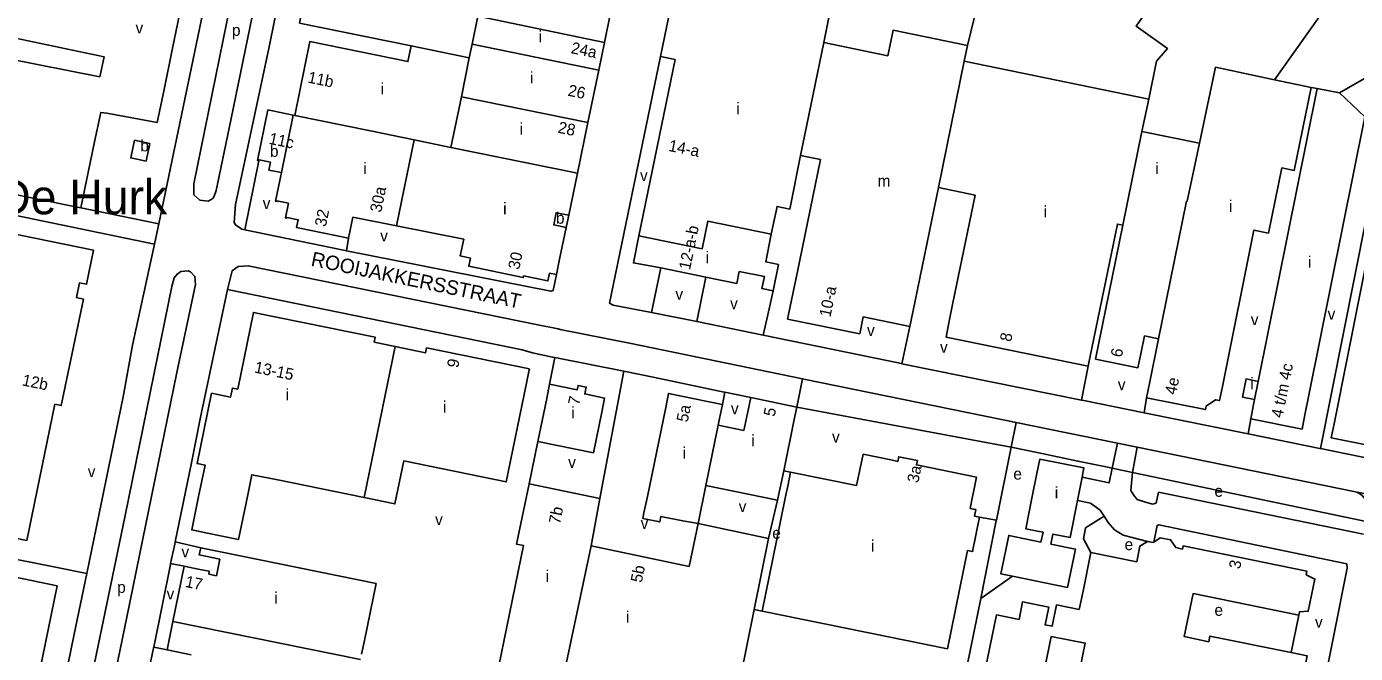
# Model space of a CAD drawing. Extents: x 157699 to 159683, y 381451 to 383293.
# Drawn here: x 158508.3 to 158968.6, y 382195.6 to 382412.9 of the extents above; entities that cross this region are included whole.
import ezdxf

# ---------------------------------------------------------------- set-up
doc = ezdxf.new("R2010")
doc.units = 0
for name, color, linetype in [('BLT_Basislijn', 7, 'Continuous'), ('BLT_Bebouwing', 7, 'Continuous'), ('BLT_Centroide', 7, 'Continuous'), ('BLT_Huisnummer', 7, 'Continuous'), ('BLT_Huisnummer_reeks', 7, 'Continuous'), ('BLT_Onderverdeling_panden', 7, 'Continuous'), ('BLT_Sport_parknaam', 7, 'Continuous'), ('BLT_Straatnaam', 7, 'Continuous')]:
    doc.layers.add(name, color=color, linetype=linetype)

msp = doc.modelspace()

# ---------------------------------------------------------------- linework, layer by layer
at = {"layer": 'BLT_Basislijn'}
for p, q in [((158572.61, 382433.33), (158554.1, 382344.5)), ((158562.84, 382424.73), (158558.87, 382405.41)), ((158834.2, 382406.33), (158836.48, 382415.8)), ((158986.18, 382403.27), (158963.05, 382389.93)), ((158953.3, 382391.8), (158955.38, 382391.47)), ((158583.87, 382342.43), (158588.74, 382366.35)), ((158501.45, 382355.29), (158511.7, 382353.19)), ((158486.34, 382351.12), (158552.63, 382337.43)), ((158511.7, 382353.19), (158522.43, 382350.98)), ((158522.43, 382350.98), (158527.1, 382350)), ((158527.1, 382350), (158554.1, 382344.5)), ((158552.63, 382337.43), (158554.1, 382344.5)), ((158619.84, 382339.52), (158619.06, 382335.14)), ((158727.99, 382329.23), (158724.76, 382313.76)), ((158743.57, 382326.04), (158740.43, 382310.59)), ((158765, 382312.9), (158766.85, 382321.28)), ((158724.76, 382313.76), (158740.43, 382310.59)), ((158763.45, 382305.87), (158765, 382312.9)), ((158740.43, 382310.59), (158763.45, 382305.87)), ((158814.26, 382308.95), (158811.51, 382296.02)), ((158717.11, 382303.09), (158693.17, 382307.91)), ((158717.11, 382303.09), (158777.08, 382290.77)), ((158689.44, 382288.89), (158691.25, 382298.12)), ((158715.13, 382293.41), (158691.25, 382298.12)), ((158811.51, 382296.02), (158873.68, 382283.41)), ((158876.04, 382295.15), (158873.68, 382283.41)), ((158715.13, 382293.41), (158706.81, 382249.34)), ((158715.13, 382293.41), (158725.36, 382291.29)), ((158775.06, 382281), (158777.08, 382290.77)), ((158749.35, 382281.86), (158750.19, 382286.1)), ((158750.19, 382286.1), (158759.11, 382284.26)), ((158775.06, 382281), (158849.34, 382267.03)), ((158895.4, 382278.98), (158896.26, 382284.2)), ((158931.38, 382271.66), (158895.4, 382278.98)), ((158931.38, 382271.66), (158932.33, 382276.93)), ((158849.34, 382267.03), (158851.05, 382275.67)), ((158886.21, 382268.5), (158851.05, 382275.67)), ((158682.37, 382254.34), (158685.39, 382269.09)), ((158844.21, 382241.74), (158849.34, 382267.03)), ((158884.34, 382259.75), (158886.21, 382268.5)), ((158886.21, 382268.5), (158893.02, 382267.13)), ((158891.33, 382258.3), (158893.02, 382267.13)), ((158968.06, 382251.75), (158893.02, 382267.13)), ((158956.46, 382266.56), (158986.47, 382260.39)), ((158772.93, 382258.45), (158770.53, 382258.89)), ((158881.04, 382260.49), (158884.34, 382259.75)), ((158884.34, 382259.75), (158891.33, 382258.3)), ((158891.33, 382258.3), (158890.77, 382252.04)), ((158891.33, 382258.3), (158972.31, 382241.32)), ((158765.25, 382235.43), (158768.45, 382248.7)), ((158890.77, 382252.04), (158891.74, 382250.55)), ((158891.74, 382250.55), (158893.01, 382248.98)), ((158893.01, 382248.98), (158895.47, 382248.09)), ((158899.57, 382247.64), (158900.34, 382251.44)), ((158971.38, 382236.96), (158900.34, 382251.44)), ((158968.06, 382251.75), (158980.78, 382249.13)), ((158895.47, 382248.09), (158898.3, 382247.27)), ((158898.3, 382247.27), (158899.57, 382247.64)), ((158838.39, 382242.79), (158844.21, 382241.74)), ((158479.27, 382233.29), (158518.84, 382225.38)), ((158568.64, 382232.22), (158559.74, 382234.23)), ((158518.84, 382225.38), (158529.12, 382223.33)), ((158562.88, 382225.83), (158558.18, 382226.72)), ((158529.12, 382223.33), (158524.79, 382202.3)), ((158824.7, 382145.3), (158838.81, 382214.57)), ((158763.08, 382210.26), (158760.28, 382210.83)), ((158946.27, 382195.85), (158949.01, 382208.79)), ((158556.95, 382196.78), (158552.33, 382197.7))]:
    msp.add_line(p, q, dxfattribs=at)
for points in [[(158533.71, 382395.49), (158535.16, 382402.41), (158495.57, 382410.69), (158488.96, 382420.8), (158500.45, 382475.74)], [(158589.92, 382433.33), (158595.48, 382460.27), (158595.51, 382461.5), (158594.69, 382463.74), (158593.67, 382464.66), (158590.55, 382465.32), (158589.18, 382464.95), (158587.53, 382462.82), (158581.51, 382433.33), (158566.21, 382358.35), (158566.28, 382354.58), (158568.34, 382352.66), (158571.2, 382352.4), (158572.77, 382353.27), (158573.3, 382354.15), (158574, 382356.06), (158578.99, 382380.49), (158589.92, 382433.33)], [(158583.87, 382342.43), (158582.82, 382342.64), (158580.69, 382344.1), (158580.25, 382344.99), (158580.69, 382351.18), (158592.27, 382405.81), (158597.9, 382433.33), (158604.02, 382463.33)], [(158558.87, 382405.41), (158555.91, 382391.09)], [(158533.71, 382395.49), (158501.04, 382401.96), (158495.93, 382377.87)], [(158727.91, 382402.53), (158710.19, 382317.05), (158711.49, 382316.32), (158724.76, 382313.76)], [(158555.91, 382391.09), (158553.54, 382379.67), (158536.07, 382382.87)], [(158536.07, 382382.87), (158533.96, 382383.11), (158531.86, 382372.98)], [(158531.86, 382372.98), (158527.1, 382350)], [(158978.31, 382375.44), (158972.33, 382346.27), (158956.46, 382266.56)], [(158619.06, 382335.14), (158618.11, 382335.33), (158583.87, 382342.43)], [(158544.99, 382302.39), (158552.63, 382337.43)], [(158619.06, 382335.14), (158689.84, 382321.11), (158690.7, 382321.39), (158691.8, 382326.9)], [(158542.98, 382208.18), (158560.31, 382292.99), (158566.84, 382323.44), (158566.59, 382326.28), (158565.09, 382327.85), (158564.24, 382328.17), (158561.69, 382328.03), (158560.4, 382327.07), (158559.37, 382325.83), (158558.61, 382322.72), (158542.49, 382243.35), (158519.79, 382134.29)], [(158577.9, 382321.69), (158579.52, 382328.25), (158581.55, 382329.74), (158585.05, 382329.95), (158685.4, 382309.5)], [(158577.9, 382321.69), (158568.46, 382276.9), (158565.47, 382261.66), (158559.74, 382234.23)], [(158577.9, 382321.69), (158680, 382300.81), (158683.55, 382299.81)], [(158685.4, 382309.5), (158692.45, 382308.05), (158693.17, 382307.91)], [(158811.51, 382296.02), (158811.29, 382296.07), (158763.45, 382305.87)], [(158544.99, 382302.39), (158541.74, 382284.55), (158529.12, 382223.33)], [(158683.55, 382299.81), (158690.43, 382298.28), (158691.25, 382298.12)], [(158750.19, 382286.1), (158749.87, 382286.16), (158725.36, 382291.29)], [(158777.08, 382290.77), (158778.05, 382290.57), (158851.05, 382275.67)], [(158873.68, 382283.41), (158874.54, 382283.24), (158895.4, 382278.98)], [(158931.38, 382271.66), (158956.24, 382266.61), (158956.46, 382266.56)], [(158849.34, 382267.03), (158858.86, 382265.07), (158872.43, 382262.28), (158881.04, 382260.49)], [(158884.34, 382259.75), (158883.27, 382254.7), (158873.87, 382256.7)], [(158881.54, 382243.13), (158880.16, 382245.28), (158876.81, 382247.65), (158872.3, 382248.63)], [(158968.06, 382251.75), (158969.02, 382251.44), (158969.97, 382250.97), (158970.86, 382250.31), (158971.64, 382249.5), (158972.27, 382248.56), (158972.72, 382247.53), (158972.98, 382246.46), (158973.05, 382245.4), (158972.96, 382244.4)], [(158838.81, 382214.57), (158844.19, 382241.64), (158844.21, 382241.74)], [(158876.98, 382230.61), (158874.35, 382235.3), (158875.07, 382239.09), (158881.54, 382243.13)], [(158896.57, 382234.41), (158888.09, 382236.56), (158885.09, 382238.46), (158882.91, 382240.98), (158881.54, 382243.13)], [(158898.79, 382234.19), (158899.9, 382239.98), (158900.48, 382240.17), (158965.55, 382226.62), (158965.66, 382225.18), (158956.72, 382179.78)], [(158559.74, 382234.23), (158559.59, 382233.49), (158558.18, 382226.72)], [(158558.18, 382226.72), (158558.11, 382226.39), (158552.33, 382197.7)], [(158849.75, 382222.35), (158838.81, 382214.57)], [(158527.49, 382132.98), (158542.98, 382208.18)], [(158524.79, 382202.3), (158518.16, 382169.99)], [(158546.04, 382167.67), (158552.26, 382197.4), (158552.33, 382197.7)]]:
    msp.add_lwpolyline(points, dxfattribs=at)
at = {"layer": 'BLT_Bebouwing'}
for p, q in [((158708.42, 382407.41), (158710.41, 382417.04)), ((158706.45, 382397.83), (158708.42, 382407.41)), ((158806.64, 382402.79), (158784.39, 382407.35)), ((158720.4, 382340.37), (158732.92, 382401.5)), ((158732.92, 382401.5), (158727.91, 382402.53)), ((158896.98, 382387.7), (158899.62, 382400.88)), ((158702.69, 382379.62), (158706.45, 382397.83)), ((158934.93, 382289.89), (158955.38, 382391.47)), ((158940.58, 382394.4), (158953.3, 382391.8)), ((158955.38, 382391.47), (158963.05, 382389.93)), ((158963.05, 382389.93), (158971.87, 382381.61)), ((158601.15, 382382.08), (158600.66, 382382.18)), ((158699.07, 382362.04), (158702.69, 382379.62)), ((158971.87, 382381.61), (158952.45, 382285.12)), ((158696.06, 382347.45), (158699.07, 382362.04)), ((158836.84, 382354.49), (158829.06, 382316.52)), ((158619.84, 382339.52), (158621.35, 382346.87)), ((158621.35, 382346.87), (158636.45, 382343.78)), ((158695.2, 382343.27), (158696.06, 382347.45)), ((158636.45, 382343.78), (158659.71, 382339.16)), ((158692.92, 382332.28), (158695.2, 382343.27)), ((158691.8, 382326.9), (158692.92, 382332.28)), ((158743.57, 382326.04), (158727.99, 382329.23)), ((158771.91, 382311.5), (158775.16, 382327.35)), ((158814.26, 382308.95), (158798.11, 382312.26)), ((158876.04, 382295.15), (158826.76, 382305.24)), ((158744.1, 382282.94), (158749.35, 382281.86)), ((158759.11, 382284.26), (158775.06, 382281)), ((158795.79, 382253.77), (158798.02, 382264.63)), ((158798.02, 382264.63), (158808.27, 382262.53)), ((158772.93, 382258.45), (158795.79, 382253.77)), ((158872.3, 382248.63), (158873.87, 382256.7)), ((158706.81, 382249.34), (158703.87, 382232.93)), ((158740.86, 382240.56), (158735.62, 382241.52)), ((158740.86, 382240.56), (158737.85, 382225.68)), ((158740.86, 382240.56), (158765.25, 382235.43)), ((158763.08, 382210.26), (158768.05, 382234.6)), ((158568.64, 382232.22), (158629.34, 382219.83)), ((158737.85, 382225.68), (158703.87, 382232.93)), ((158874.23, 382217.15), (158876.98, 382230.61)), ((158562.88, 382225.83), (158558.96, 382206.64)), ((158571.37, 382223.02), (158574.03, 382222.48)), ((158518.94, 382219.05), (158506, 382156.09)), ((158872.92, 382210.76), (158874.23, 382217.15)), ((158912.32, 382216.31), (158949.01, 382208.79)), ((158827.26, 382197.14), (158763.08, 382210.26)), ((158558.96, 382206.64), (158556.95, 382196.78)), ((158625.29, 382200.03), (158624.32, 382195.29)), ((158556.95, 382196.78), (158565.25, 382195.09))]:
    msp.add_line(p, q, dxfattribs=at)
for points in [[(158874.88, 382462.18), (158861.4, 382443.14), (158875.11, 382433.33), (158896.35, 382418.39), (158892.59, 382413.03), (158903.43, 382405.33), (158901.23, 382402.76)], [(158727.91, 382402.53), (158734.86, 382436.77)], [(158940.58, 382394.4), (158968.06, 382433.23)], [(158604.7, 382423.28), (158602.83, 382414.12), (158641.48, 382406.21)], [(158788.16, 382425.83), (158784.39, 382407.35)], [(158806.64, 382402.79), (158808.44, 382411.61), (158834.2, 382406.33)], [(158641.48, 382406.21), (158640.36, 382400.73), (158606.39, 382407.68), (158601.15, 382382.08)], [(158833.1, 382400.94), (158834.2, 382406.33)], [(158833.1, 382400.94), (158896.98, 382387.7)], [(158901.23, 382402.76), (158899.62, 382400.88)], [(158953.3, 382391.8), (158947.41, 382363.04), (158943.04, 382363.94)], [(158600.66, 382382.18), (158591.91, 382383.98), (158588.32, 382366.43), (158588.74, 382366.35)], [(158549.68, 382366.23), (158544.4, 382367.33), (158545.68, 382373.49), (158550.96, 382372.39), (158549.68, 382366.23)], [(158776.4, 382368.16), (158772.61, 382349.64), (158768.23, 382350.54), (158766.25, 382340.88)], [(158776.4, 382368.16), (158783.24, 382366.76)], [(158588.74, 382366.35), (158588.81, 382366.69), (158592.77, 382365.88), (158592.22, 382363.16), (158596.58, 382362.27)], [(158775.16, 382327.35), (158783.24, 382366.76)], [(158896.26, 382284.2), (158916.61, 382280.08), (158916.87, 382281.32), (158920.16, 382283.5), (158921.48, 382283.23), (158922.48, 382288.13), (158933.44, 382342.31), (158938.45, 382341.3), (158943.04, 382363.94)], [(158596.58, 382362.27), (158594.54, 382352.31), (158594.98, 382352.22), (158595.02, 382352.43), (158598.96, 382351.62)], [(158824.12, 382357.09), (158815.26, 382313.85), (158814.26, 382308.95)], [(158836.84, 382354.49), (158824.12, 382357.09)], [(158486.34, 382351.12), (158485.06, 382344.86), (158531.46, 382335.37), (158529.01, 382323.57), (158526.65, 382324.06), (158525.58, 382318.93), (158527.95, 382318.43), (158520.28, 382281.49), (158518.09, 382281.94), (158508.38, 382234.73), (158390.67, 382258.79)], [(158598.96, 382351.62), (158597.93, 382346.59), (158598.37, 382346.5), (158598.41, 382346.71), (158602.37, 382345.9), (158601.82, 382343.21), (158619.84, 382339.52)], [(158727.99, 382329.23), (158718.5, 382330.96), (158720.4, 382340.37)], [(158766.25, 382340.88), (158764.3, 382331.34), (158768.72, 382330.44)], [(158888.03, 382344.01), (158886.12, 382344.4), (158876.62, 382297.99)], [(158878.53, 382297.6), (158888.03, 382344.01)], [(158983.58, 382270.68), (158997.24, 382339.24), (158974.85, 382343.71), (158961.19, 382275.18), (158960.22, 382270.28), (158982.61, 382265.78), (158983.58, 382270.68)], [(158659.71, 382339.16), (158658.51, 382333.36), (158662.01, 382332.64), (158661.42, 382329.8), (158680.35, 382325.88), (158680.46, 382326.43), (158688.86, 382324.69), (158689.42, 382327.39), (158691.8, 382326.9)], [(158755.16, 382328.03), (158754.3, 382323.84), (158743.57, 382326.04)], [(158766.85, 382321.28), (158763, 382322.07), (158763.85, 382326.25), (158755.16, 382328.03)], [(158768.72, 382330.44), (158766.85, 382321.28)], [(158625.25, 382249.58), (158595.28, 382255.7), (158586.3, 382257.54), (158584.76, 382250), (158581.67, 382235.07), (158570.41, 382237.37), (158565.51, 382238.37), (158567.89, 382250), (158570.11, 382260.84), (158567.37, 382261.4), (158572.37, 382285.79), (158578.96, 382284.44), (158579.61, 382287.57), (158581.41, 382287.2), (158586.86, 382313.8), (158629.04, 382305.17), (158628.69, 382303.48), (158636.01, 382301.98)], [(158826.76, 382305.24), (158827.76, 382310.14), (158829.06, 382316.52)], [(158798.11, 382312.26), (158796.91, 382306.38), (158771.91, 382311.5)], [(158895.49, 382305.62), (158894.24, 382299.48), (158893.24, 382294.59), (158878.53, 382297.6)], [(158895.49, 382305.62), (158900.39, 382304.59)], [(158900.39, 382304.59), (158897.25, 382289.1), (158896.26, 382284.2)], [(158636.01, 382301.98), (158646.49, 382299.83), (158646.83, 382301.47), (158682.45, 382294.18)], [(158876.62, 382297.99), (158876.04, 382295.15)], [(158682.45, 382294.18), (158682.4, 382293.85), (158681.46, 382289.27), (158674.44, 382255.02), (158638.93, 382262.29), (158635.88, 382247.41), (158625.25, 382249.58)], [(158934.93, 382289.89), (158930.71, 382290.75), (158929.42, 382284.46), (158933.67, 382283.59)], [(158685.39, 382269.09), (158688.44, 382283.99), (158689.44, 382288.89)], [(158689.44, 382288.89), (158699, 382286.93), (158699.32, 382288.5), (158702.13, 382287.93), (158701.64, 382285.53), (158708.51, 382284.12), (158707.51, 382279.22), (158704.63, 382265.15), (158685.39, 382269.09)], [(158744.1, 382282.94), (158730.68, 382285.69), (158729.67, 382280.79), (158723.33, 382250), (158722.15, 382244.29), (158721.76, 382242.33), (158727.63, 382241.16), (158728.03, 382243.08), (158735.62, 382241.52)], [(158952.45, 382285.12), (158951.07, 382278.26), (158950.08, 382273.36), (158932.33, 382276.93)], [(158749.35, 382281.86), (158748.34, 382276.97), (158747.88, 382274.71)], [(158756.78, 382272.88), (158758.11, 382279.36), (158759.11, 382284.26)], [(158775.06, 382281), (158774.17, 382276.68), (158770.53, 382258.89)], [(158932.33, 382276.93), (158933.31, 382281.84), (158933.67, 382283.59)], [(158756.78, 382272.88), (158747.88, 382274.71)], [(158808.27, 382262.53), (158810.05, 382262.16), (158810.38, 382263.77), (158816.84, 382262.44)], [(158816.84, 382262.44), (158816.53, 382260.91), (158837.35, 382256.65), (158836.41, 382252.08), (158835.99, 382250), (158835.18, 382245.87)], [(158873.87, 382256.7), (158874.5, 382259.93), (158859.27, 382262.89), (158858.27, 382257.99), (158856.66, 382250), (158854.39, 382238.77), (158858.45, 382237.98)], [(158768.05, 382234.6), (158771.2, 382250), (158771.93, 382253.55), (158772.93, 382258.45)], [(158770.53, 382258.89), (158768.45, 382248.7)], [(158671.81, 382190.67), (158680.46, 382232.95), (158678.02, 382233.45), (158682.37, 382254.34)], [(158682.37, 382254.34), (158706.81, 382249.34)], [(158743.58, 382253.78), (158740.86, 382240.56)], [(158768.45, 382248.7), (158743.58, 382253.78)], [(158872.3, 382248.63), (158869.8, 382235.77), (158863.79, 382236.94), (158863.09, 382233.5), (158871.61, 382231.76), (158868.88, 382218.45), (158849.75, 382222.35)], [(158835.18, 382245.87), (158837.06, 382245.49), (158836.59, 382243.16), (158838.39, 382242.79)], [(158838.39, 382242.79), (158835.96, 382230.89), (158834.23, 382231.24), (158827.26, 382197.14)], [(158765.25, 382235.43), (158760.28, 382210.83)], [(158849.75, 382222.35), (158845.76, 382223.16), (158848.49, 382236.46), (158859.66, 382234.17), (158860.37, 382237.61), (158858.45, 382237.98)], [(158898.79, 382234.19), (158900.92, 382235.65), (158904.54, 382234.9), (158906.33, 382232.26), (158908.64, 382231.71)], [(158464.62, 382228.97), (158464.88, 382230.25), (158518.94, 382219.05)], [(158568.64, 382232.22), (158568.1, 382229.75), (158575.26, 382228.21), (158574.03, 382222.48)], [(158876.98, 382230.61), (158892.82, 382227.34), (158893.87, 382232.78), (158896.57, 382234.41)], [(158896.57, 382234.41), (158898.6, 382234.06), (158898.79, 382234.19)], [(158908.64, 382231.71), (158908.87, 382232.84), (158951.76, 382224.04), (158951.54, 382222.84), (158954.54, 382221.35), (158952.25, 382210.19), (158949.23, 382210), (158949.01, 382208.79)], [(158571.37, 382223.02), (158571.58, 382224.05), (158567.78, 382224.83), (158562.88, 382225.83)], [(158629.34, 382219.83), (158625.29, 382200.03)], [(158946.27, 382195.85), (158918.17, 382201.61), (158917.77, 382199.64), (158909.26, 382201.39), (158912.32, 382216.31)], [(158844.22, 382208.94), (158852.05, 382207.34), (158853.31, 382213.49), (158862.35, 382211.64), (158861.09, 382205.48), (158863.48, 382204.99), (158864.99, 382212.38), (158872.92, 382210.76)], [(158760.28, 382210.83), (158752.99, 382174.76)], [(158830.4, 382143.62), (158834.71, 382142.74), (158835.71, 382147.65), (158831.82, 382148.44), (158844.22, 382208.94)], [(158954.93, 382180.14), (158955.95, 382185.11), (158950.88, 382186.15), (158951.66, 382189.97), (158950.93, 382190.12), (158951.87, 382194.71), (158946.27, 382195.85)]]:
    msp.add_lwpolyline(points, dxfattribs=at)
msp.add_lwpolyline([(158863.2, 382201.49), (158874.97, 382199.14), (158868.14, 382165.84), (158856.44, 382168.27)], close=True, dxfattribs=at)
at = {"layer": 'BLT_Onderverdeling_panden'}
for p, q in [((158664.6, 382416.49), (158662.61, 382406.8)), ((158664.6, 382416.49), (158708.42, 382407.41)), ((158641.48, 382406.21), (158661.65, 382402.08)), ((158662.61, 382406.8), (158661.65, 382402.08)), ((158662.61, 382406.8), (158706.45, 382397.83)), ((158661.65, 382402.08), (158658.89, 382388.58)), ((158833.1, 382400.94), (158824.12, 382357.09)), ((158920.07, 382398.76), (158914.51, 382372.45)), ((158920.07, 382398.76), (158940.58, 382394.4)), ((158658.89, 382388.58), (158655.28, 382370.98)), ((158658.89, 382388.58), (158702.69, 382379.62)), ((158896.98, 382387.7), (158894.63, 382376.54)), ((158600.66, 382382.18), (158596.58, 382362.27)), ((158601.15, 382382.08), (158627.45, 382376.7)), ((158627.45, 382376.7), (158642.55, 382373.59)), ((158642.55, 382373.59), (158636.45, 382343.78)), ((158642.55, 382373.59), (158655.28, 382370.98)), ((158894.63, 382376.54), (158888.03, 382344.01)), ((158894.63, 382376.54), (158914.51, 382372.45)), ((158655.28, 382370.98), (158699.07, 382362.04)), ((158636.01, 382301.98), (158625.25, 382249.58)), ((158933.67, 382283.59), (158934.93, 382289.89)), ((158703.87, 382232.93), (158694.03, 382186.49)), ((158623.95, 382193.48), (158558.96, 382206.64))]:
    msp.add_line(p, q, dxfattribs=at)
for points in [[(158784.39, 382407.35), (158776.4, 382368.16)], [(158914.51, 382372.45), (158910.34, 382352.36), (158910.07, 382352.41), (158900.39, 382304.59)], [(158696.06, 382347.45), (158691.72, 382348.34), (158690.87, 382344.15), (158695.2, 382343.27)], [(158720.4, 382340.37), (158742.27, 382335.89), (158744.21, 382345.4), (158766.25, 382340.88)], [(158747.88, 382274.71), (158743.58, 382253.78)]]:
    msp.add_lwpolyline(points, dxfattribs=at)

# ---------------------------------------------------------------- texts
at = {"layer": 'BLT_Centroide'}
for s, p in [('v', (158546.03, 382410.5)), ('p', (158579.42, 382409.66)), ('i', (158685.64, 382407.44)), ('i', (158682.7, 382393.16)), ('i', (158630.88, 382389.34)), ('i', (158754.16, 382382.5)), ('i', (158679.06, 382375.47)), ('b', (158547.68, 382369.62)), ('b', (158592.59, 382367.72)), ('i', (158624.96, 382361.75)), ('i', (158899.3, 382361.73)), ('v', (158720.77, 382359.33)), ('m', (158803.06, 382357.39)), ('v', (158590.08, 382349.68)), ('i', (158673.35, 382347.84)), ('i', (158860.55, 382346.78)), ('i', (158924.78, 382348.64)), ('b', (158691.65, 382344.54)), ('v', (158630.78, 382338.4)), ('i', (158743.48, 382330.84)), ('i', (158952.09, 382329.27)), ('v', (158733.03, 382318.18)), ('v', (158751.96, 382314.91)), ('v', (158958.94, 382311.27)), ('v', (158799.4, 382305.63)), ('v', (158932.33, 382309.39)), ('v', (158824.68, 382299.79)), ('v', (158886.28, 382286.82)), ('i', (158932.17, 382287.17)), ('i', (158598.06, 382283.31)), ('i', (158652.52, 382279.06)), ('i', (158696.95, 382277.03)), ('v', (158752.26, 382278.47)), ('i', (158759.31, 382267.39)), ('v', (158787.28, 382268.68)), ('i', (158735.55, 382263.11)), ('v', (158695.88, 382259.86)), ('v', (158529.46, 382256.71)), ('e', (158850.08, 382255.85)), ('i', (158864.44, 382249.34)), ('e', (158919.74, 382249.89)), ('v', (158754.96, 382244.57)), ('v', (158649.79, 382240.07)), ('v', (158720.98, 382238.76)), ('e', (158766.59, 382235.31)), ('i', (158800.73, 382230.88)), ('e', (158888.62, 382231.38)), ('v', (158561.93, 382228.83)), ('i', (158688.08, 382220.39)), ('p', (158539.66, 382216.56)), ('v', (158556.78, 382214.29)), ('i', (158594.07, 382212.84)), ('e', (158919.74, 382208.62)), ('i', (158715.94, 382206.23)), ('v', (158954.57, 382204.49))]:
    msp.add_text(s, height=4, dxfattribs=at).set_placement(p)
at = {"layer": 'BLT_Huisnummer'}
for s, rotation, p in [('24a', 348.4146, (158696.61, 382403.7)), ('11b', 348.4309, (158605.44, 382393.5)), ('26', 348.4309, (158695.57, 382388.95)), ('28', 348.2996, (158692.11, 382376.13)), ('11c', 348.4301, (158592, 382372.27)), ('30', 78.2834, (158678.92, 382328.45)), ('8', 78.4282, (158849.27, 382303.41)), ('6', 78.4294, (158887.63, 382298.02)), ('9', 78.4275, (158657.76, 382294.36)), ('12b', 348.4264, (158506.53, 382288.53)), ('4e', 78.5546, (158906.4, 382285.04)), ('7', 78.4264, (158699.7, 382281.4)), ('5a', 78.4326, (158737.24, 382275.52)), ('5', 78.4326, (158767.4, 382277.47)), ('3a', 78.4194, (158817.14, 382254.49)), ('7b', 78.4264, (158693.03, 382240.19)), ('5b', 78.4326, (158721.37, 382219.88)), ('17', 348.5542, (158563, 382218.66))]:
    msp.add_text(s, height=4, rotation=rotation, dxfattribs=at).set_placement(p)
at = {"layer": 'BLT_Huisnummer_reeks'}
for s, rotation, p in [('14-a', 348.4292, (158730.42, 382369.81)), ('30a', 78.4326, (158631.09, 382348.23)), ('32', 78.4326, (158611.94, 382343.27)), ('12-a-b', 78.4273, (158738.09, 382328.33)), ('10-a', 78.4335, (158786.71, 382311.95)), ('13-15', 348.4264, (158586.96, 382292.99)), ('4 t/m 4c', 78.7335, (158943.28, 382277.02)), ('3', 78.4119, (158928.59, 382224.6))]:
    msp.add_text(s, height=4, rotation=rotation, dxfattribs=at).set_placement(p)
at = {"layer": 'BLT_Sport_parknaam'}
msp.add_text('Bedrijventerrein De Hurk', height=12, dxfattribs=at).set_placement((158381.28, 382347.82))
at = {"layer": 'BLT_Straatnaam'}
msp.add_text('ROOIJAKKERSSTRAAT', height=5, rotation=348.3664, dxfattribs=at).set_placement((158606.53, 382330.01))

doc.saveas('drawing.dxf')
